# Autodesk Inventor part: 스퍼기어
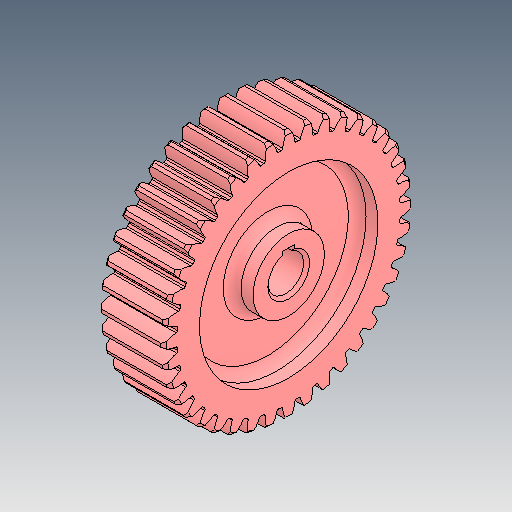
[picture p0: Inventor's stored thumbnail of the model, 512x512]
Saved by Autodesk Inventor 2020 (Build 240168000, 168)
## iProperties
Created: 2024-11
Part Number: 스퍼기어
Material: 강철, 탄소
Document SubType Name: Modeling
Designer: shin
Density: 7.85 g/cm^3
Appearance: 기본값
Author: jhkim
Sending System: Autodesk Inventor 2025
Preprocessor: ST-DEVELOPER v20
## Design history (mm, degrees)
feature "솔리드1"
node "솔리드2"
